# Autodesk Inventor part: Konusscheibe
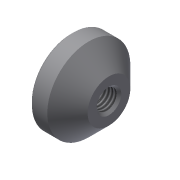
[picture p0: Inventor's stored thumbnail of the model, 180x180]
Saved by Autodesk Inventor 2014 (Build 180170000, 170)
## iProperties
Company: VDW-Nachwuchsstiftung
Created: 2014-03
Part Number: Konusscheibe
Material: Generisch
Document SubType Name: Modeling
Designer: e_dammj
Density: 1 g/cm^3
Appearance: Vorgabe
Author: e_dammj
Title: Konusscheibe
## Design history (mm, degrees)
sketch "Skizze1"
  geometry: L1 (0, 0)-(0, 9); L2 (0, 9)-(-8.5, 17.5); L3 (-8.5, 17.5)-(-16, 17.5); L4 (-16, 17.5)-(-16, 0); L5 (-16, 0)-(0, 0) reference; 1 further point
  constraints: 10 end point, 2 perpendicular, 1 coincident, 1 horizontal, 1 parallel
  dimensions: "d0" = 16 distance between parallel lines of L4 L1; "d1" = 45 deg angle of L1 L2; "d2" = 18 diameter of L1.end L5; "d3" = 35 diameter of L3 L5
revolve "Umdrehung1" sketch "Skizze1" stored, may be unused: angle "d4" = 90 deg
sketch "Skizze2"
  geometry: C1 r 17.5 at (0, 0) reference; 1 further point
  constraints: 1 coincident
hole "Bohrung1" sketch "Skizze2" at (0, 0) diameter "d5" = 8.376; stored, may be unused: countersink angle "d9" = 90 deg, drill point angle "d11" = 118 deg; dims "d6" = 6, "d7" = 4, "d8" = 2, "d10" = 8
chamfer "Fase1" distance "d12" = 1; stored, may be unused: second distance "d13" = 2, angle "d14" = 45 deg
node "Volumenkörper1"
